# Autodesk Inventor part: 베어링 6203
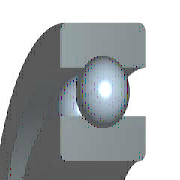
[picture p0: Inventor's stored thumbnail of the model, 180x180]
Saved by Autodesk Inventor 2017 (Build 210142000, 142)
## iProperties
IsCustomPart: 0
Created: 2014-10
Part Number: 베어링 6203
Material: 강철, 연강
Description: 깊은 그루브 볼 베어링
Document SubType Name: Modeling
Standard: KS B 2023
Designer: KYOUNG IL JANG
Standards Organization: KS
Language: ko-KR
Size Designation: 6203 - 17 x 40 x 12
Categories: <MemberInstance><Categories><Category DisplayName="샤프트 부품" InternalName="7f7aeb1f-a693-4053-b835-cee3144e0d98" Mnemonic="SHFT"><Category DisplayName="베어링" Inter
Density: 7.86 g/cm^3
Mass: 64.9809 g
Surface Area: 64.3582 cm^2
Volume: 8.26729 cm^3
Appearance: 노란색
Author: SeoGD™ [www.esajin.kr]
Revision Number: 1
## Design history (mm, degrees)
sketch "스케치" dims "d0" = 5.98 (= -0.26 x WD + 0.26 x BD)
  geometry: L1 (3.01, 14.25)-(8.99, 14.25); L2 (6, 14.25)-(6, 11.26); L3 (6, 14.25)-(6, 17.24); L4 (3.778, 12.249)-(0, 12.249); L5 (0, 8.5)-(12, 8.5); L6 (3.778, 16.251)-(0, 16.251); L7 (0, 20)-(12, 20); L8 (12, 8.5)-(12, 12.249); L9 (8.222, 12.249)-(12, 12.249); L10 (8.222, 16.251)-(12, 16.251); L11 (12, 20)-(12, 16.251); L12 (-1.4, 0)-(8.4, 0) reference; L13 (0, -0.3)-(0, 5.3) reference
  constraints: 22 end point, 4 point on line, 2 collinear, 2 perpendicular, 2 symmetric about line, 1 midpoint, 1 parallel, 14 other
  dimensions: "d9" = 17 diameter of L5 L12 (= WD); "d11" = 40 diameter of L7 L12 (= BD); "d12" = 12 distance between parallel lines of L8 L13 (= KB); "d13" = 24.498 diameter of L9 L12 (= 0.326 x BD + 0.674 x WD)
revolve "본체" stored, may be unused: angle "d6" = 90 deg
revolve "볼" stored, may be unused: angle "d7" = 90 deg
pattern_circular "IDS_ARRAYBALL[SIMPL:T]" dims angle "d3" = 360 deg
body "Solid1"
fillet "모깎기1" dims "d1" = 0.6 (= KRS)
other parameters: "WD" = 17 [user parameter; used in 5 equation terms], "BD" = 40 [user parameter; used in 5 equation terms], "KB" = 12 [user parameter; used in 1 equation term], "KRS" = 0.6 [user parameter; used in 1 equation term], "d4" = 0, "d5" = 0, "d8" = 0, "d14" = 0, "d15" = 0, "BBA" = 0 [user parameter], "BC0" = 4750000 [user parameter], "BC" = 9560000 [user parameter], "WR" = 8.5 (= 0.5 x WD) [user parameter]
